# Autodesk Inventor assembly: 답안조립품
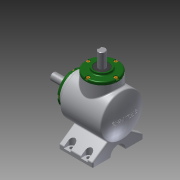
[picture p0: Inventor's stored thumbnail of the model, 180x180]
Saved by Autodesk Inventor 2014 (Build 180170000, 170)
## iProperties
Created: 2017-04
Part Number: 답안조립품
Document SubType Name: Assembly
Designer: user
Author: user
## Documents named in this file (14)
- C:\Users\user\Desktop\470408V1011\답안조립품.iam
- C:\Users\user\Desktop\470408V1011\본체.ipt
- C:\Users\user\Desktop\470408V1011\커버.ipt
- C:\Users\user\Desktop\470408V1011\볼트 M4.ipt
- C:\Users\user\Desktop\470408V1011\오일실 17 32 8.ipt
- C:\Users\user\Desktop\470408V1011\베어링 6203.ipt
- C:\Users\user\Desktop\470408V1011\메인 축.ipt
- 메인 축.ipt
- C:\Users\user\Desktop\470408V1011\서브 축.ipt
- 서브 축.ipt
- C:\Users\user\Desktop\470408V1011\키 5x5.ipt
- C:\Users\user\Desktop\470408V1011\키 4x4.ipt
- C:\Users\user\Desktop\470408V1011\메인 베벨기어.ipt
- C:\Users\user\Desktop\470408V1011\서브 베벨기어.ipt
